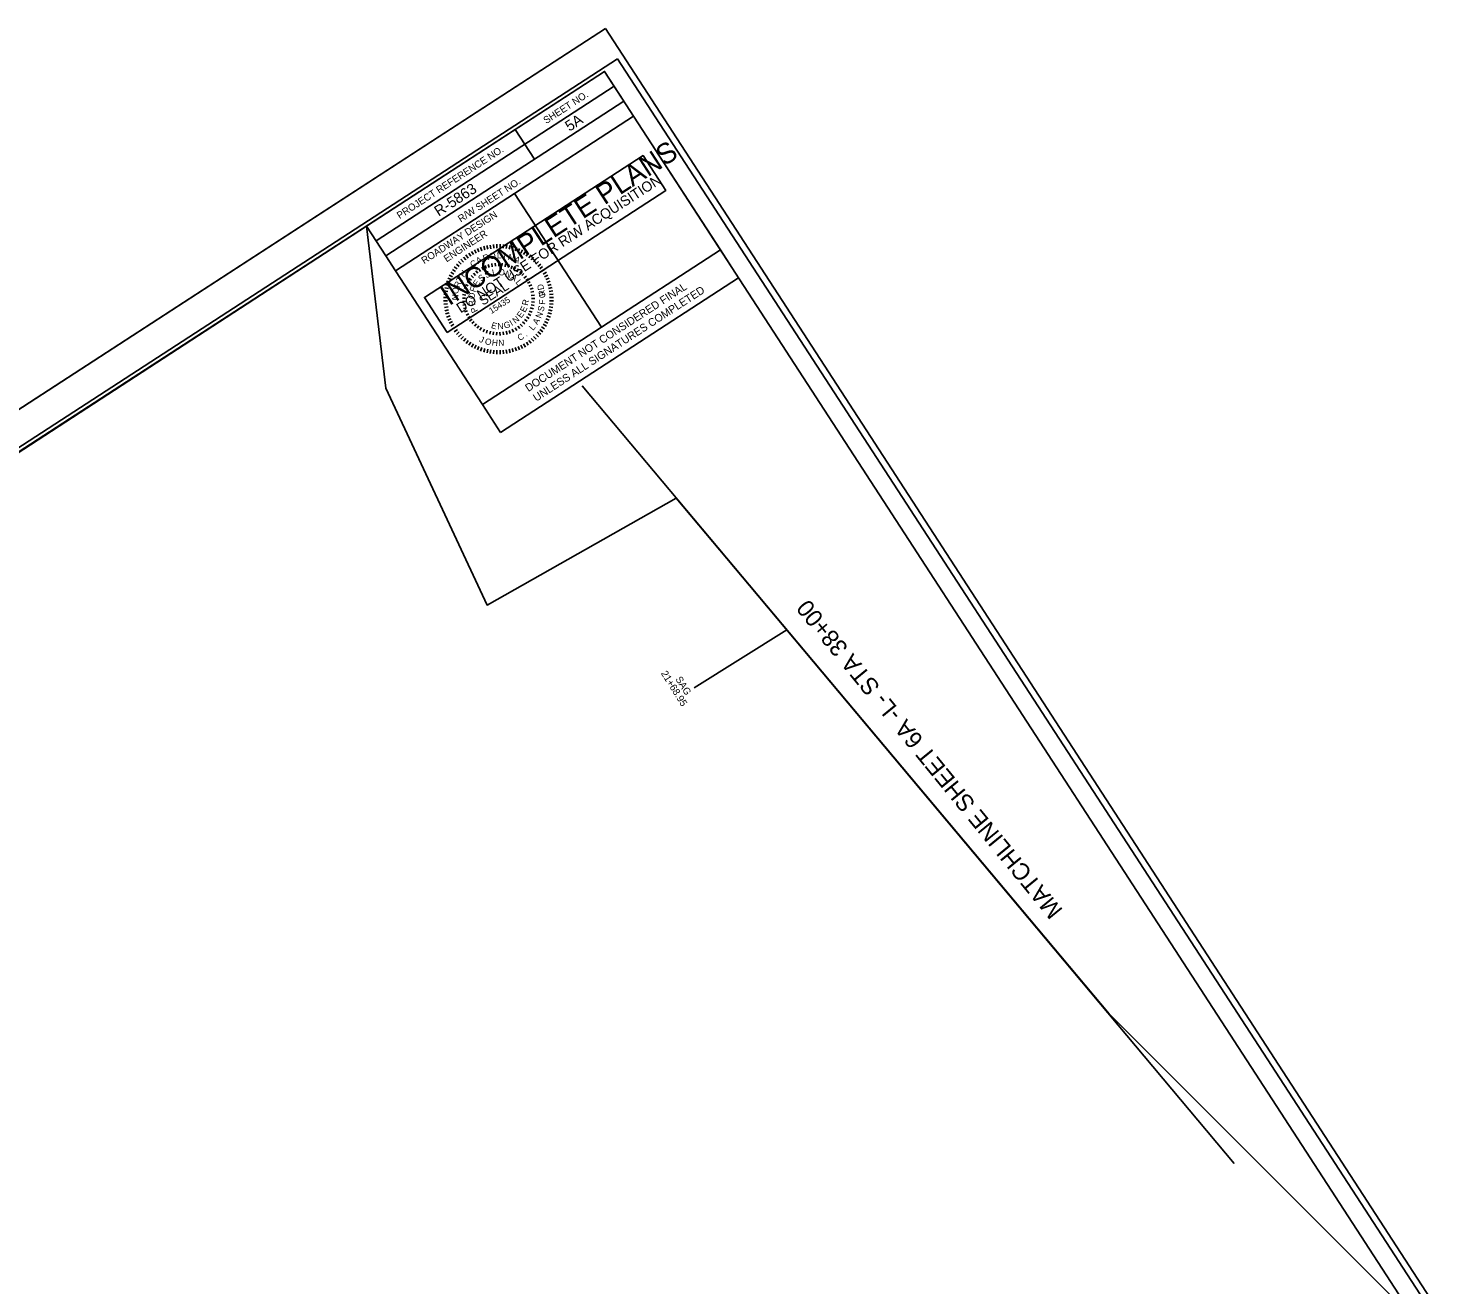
# Model space of a CAD drawing. Extents: x 555170 to 557181, y 503234 to 505074.
# Drawn here: x 556175 to 557181, y 504189 to 505074 of the extents above; entities that cross this region are included whole.
import ezdxf

# ---------------------------------------------------------------- set-up
doc = ezdxf.new("R2010")
doc.units = 0
for name, color, linetype in [('Exist Horizontal Alignment', 7, 'Continuous'), ('Old_Level_2', 7, 'Continuous'), ('Pattern 1', 7, 'Continuous'), ('Prop Horizontal Alignment', 7, 'Continuous'), ('Prop Horizontal Alignment Curve and Spiral Data', 7, 'Continuous'), ('Prop Paved Shoulder', 7, 'Continuous'), ('Prop Roadway Bridge', 7, 'Continuous'), ('Prop Superelevation Label', 7, 'Continuous'), ('Scratch_Level_4', 7, 'Continuous'), ('Sheet North Arrow CELL', 7, 'Continuous'), ('Sheet Plot Border Inside CELL', 7, 'Continuous'), ('Sheet Plot Border Outside CELL', 7, 'Continuous')]:
    doc.layers.add(name, color=color, linetype=linetype)

msp = doc.modelspace()

# ---------------------------------------------------------------- linework, layer by layer
at = {"layer": 'Exist Horizontal Alignment'}
msp.add_lwpolyline([(556581.9, 505074), (555169.6, 504156.8), (555768.7, 503234.3), (557181.1, 504151.5)], close=True, dxfattribs=at)
at = {"layer": 'Old_Level_2'}
msp.add_line((556709.9, 504650), (556644.6, 504609.3), dxfattribs=at)
at = {"layer": 'Pattern 1'}
for p, q in [((556489.6, 504918), (556490.8, 504915.6)), ((556491.8, 504918.9), (556492.8, 504916.5)), ((556493.9, 504919.8), (556494.8, 504917.3)), ((556496.2, 504920.5), (556496.9, 504917.9)), ((556498.4, 504921), (556499, 504918.4)), ((556500.7, 504921.4), (556501.1, 504918.8)), ((556503.1, 504921.7), (556503.3, 504919.1)), ((556505.4, 504921.9), (556505.5, 504919.2)), ((556507.7, 504921.9), (556507.7, 504919.2)), ((556510.1, 504921.7), (556509.8, 504919.1)), ((556512.4, 504921.5), (556512, 504918.9)), ((556514.7, 504921), (556514.1, 504918.5)), ((556517, 504920.5), (556516.2, 504917.9)), ((556519.2, 504919.8), (556518.3, 504917.3)), ((556521.4, 504919), (556520.4, 504916.5)), ((556523.5, 504918), (556522.4, 504915.6)), ((556476.9, 504908), (556478.9, 504906.3)), ((556478.4, 504909.7), (556480.3, 504907.9)), ((556480.1, 504911.4), (556481.9, 504909.4)), ((556481.8, 504912.9), (556483.5, 504910.9)), ((556483.6, 504914.4), (556485.2, 504912.2)), ((556485.6, 504915.7), (556487, 504913.5)), ((556487.6, 504916.9), (556488.9, 504914.6)), ((556501.8, 504908.3), (556502.2, 504906.1)), ((556504.3, 504908.6), (556504.5, 504906.4)), ((556506.7, 504908.7), (556506.7, 504906.5)), ((556509.2, 504908.6), (556509, 504906.4)), ((556511.6, 504908.2), (556511.2, 504906)), ((556525.6, 504916.9), (556524.3, 504914.6)), ((556527.6, 504915.7), (556526.1, 504913.5)), ((556529.5, 504914.4), (556527.9, 504912.3)), ((556531.3, 504912.9), (556529.6, 504910.9)), ((556533.1, 504911.4), (556531.3, 504909.5)), ((556534.7, 504909.7), (556532.8, 504907.9)), ((556536.3, 504908), (556534.3, 504906.3)), ((556470.8, 504898), (556473.3, 504897)), ((556471.8, 504900.1), (556474.2, 504899)), ((556472.9, 504902.2), (556475.2, 504900.9)), ((556474.1, 504904.2), (556476.3, 504902.8)), ((556475.4, 504906.1), (556477.5, 504904.6)), ((556485.7, 504897.8), (556487.5, 504896.6)), ((556487.2, 504899.8), (556488.9, 504898.3)), ((556488.9, 504901.6), (556490.4, 504900)), ((556490.7, 504903.2), (556492.1, 504901.5)), ((556492.7, 504904.6), (556493.9, 504902.8)), ((556493.9, 504902.8), (556492.7, 504904.6)), ((556494.9, 504905.9), (556495.9, 504903.9)), ((556497.1, 504906.9), (556497.9, 504904.8)), ((556499.4, 504907.7), (556500, 504905.6)), ((556514, 504907.6), (556513.4, 504905.5)), ((556516.3, 504906.8), (556515.5, 504904.7)), ((556518.6, 504905.7), (556517.5, 504903.8)), ((556520.7, 504904.5), (556519.5, 504902.6)), ((556522.7, 504903), (556521.3, 504901.3)), ((556524.5, 504901.4), (556523, 504899.8)), ((556526.2, 504899.5), (556524.5, 504898.1)), ((556537.7, 504906.2), (556535.6, 504904.6)), ((556539.1, 504904.2), (556536.8, 504902.8)), ((556540.3, 504902.2), (556538, 504900.9)), ((556541.4, 504900.2), (556539, 504899)), ((556542.3, 504898), (556539.9, 504897)), ((556468.3, 504889), (556470.9, 504888.6)), ((556468.8, 504891.3), (556471.3, 504890.8)), ((556469.3, 504893.6), (556471.9, 504892.9)), ((556470, 504895.8), (556472.5, 504895)), ((556481.7, 504888.8), (556483.9, 504888.4)), ((556482.4, 504891.2), (556484.5, 504890.5)), ((556483.3, 504893.5), (556485.3, 504892.6)), ((556484.4, 504895.7), (556486.3, 504894.6)), ((556527.7, 504897.6), (556525.8, 504896.3)), ((556528.9, 504895.5), (556527, 504894.4)), ((556528, 504892.5), (556530, 504893.3)), ((556530.9, 504891), (556528.8, 504890.3)), ((556531.5, 504888.6), (556529.4, 504888.1)), ((556543.1, 504895.9), (556540.7, 504895)), ((556543.8, 504893.6), (556541.3, 504892.9)), ((556544.4, 504891.4), (556541.8, 504890.8)), ((556544.8, 504889.1), (556542.2, 504888.7)), ((556467.9, 504884.4), (556470.6, 504884.3)), ((556467.9, 504882), (556470.6, 504882.1)), ((556468.1, 504886.7), (556470.7, 504886.5)), ((556468.1, 504879.7), (556470.7, 504879.9)), ((556468.4, 504877.4), (556471, 504877.8)), ((556481.1, 504884), (556483.3, 504883.9)), ((556481.2, 504881.5), (556483.3, 504881.6)), ((556481.3, 504886.4), (556483.5, 504886.1)), ((556481.4, 504879.1), (556483.6, 504879.4)), ((556531.7, 504878.8), (556529.5, 504879.2)), ((556531.9, 504886.1), (556529.7, 504885.9)), ((556532, 504881.2), (556529.8, 504881.4)), ((556532.1, 504883.7), (556529.9, 504883.6)), ((556544.8, 504877.4), (556542.2, 504877.8)), ((556545.1, 504886.7), (556542.5, 504886.5)), ((556545.1, 504879.7), (556542.5, 504880)), ((556545.3, 504884.4), (556542.6, 504884.3)), ((556545.3, 504882.1), (556542.6, 504882.1)), ((556468.8, 504875.1), (556471.4, 504875.6)), ((556469.3, 504872.8), (556471.9, 504873.5)), ((556470, 504870.6), (556472.5, 504871.4)), ((556470.9, 504868.4), (556473.3, 504869.4)), ((556482, 504876.6), (556484.1, 504877.2)), ((556482.7, 504874.3), (556484.8, 504875.1)), ((556483.7, 504872), (556485.6, 504873)), ((556484.9, 504869.9), (556486.7, 504871)), ((556486.2, 504867.8), (556488, 504869.2)), ((556526.8, 504867.6), (556525, 504869)), ((556528.2, 504869.6), (556526.3, 504870.8)), ((556529.4, 504871.8), (556527.4, 504872.8)), ((556530.4, 504874), (556528.3, 504874.8)), ((556531.2, 504876.4), (556529, 504877)), ((556542.3, 504868.4), (556539.9, 504869.4)), ((556543.2, 504870.6), (556540.7, 504871.5)), ((556543.9, 504872.9), (556541.3, 504873.6)), ((556544.4, 504875.1), (556541.8, 504875.7)), ((556471.8, 504866.3), (556474.2, 504867.4)), ((556472.9, 504864.2), (556475.2, 504865.5)), ((556474.1, 504862.2), (556476.3, 504863.6)), ((556475.4, 504860.3), (556477.6, 504861.8)), ((556476.9, 504858.4), (556478.9, 504860.1)), ((556478.4, 504856.7), (556480.4, 504858.5)), ((556487.8, 504866), (556489.4, 504867.4)), ((556489.6, 504864.2), (556491, 504865.9)), ((556491.5, 504862.7), (556492.8, 504864.4)), ((556493.5, 504861.3), (556494.7, 504863.2)), ((556495.7, 504860.2), (556496.7, 504862.1)), ((556498, 504859.2), (556498.7, 504861.3)), ((556500.4, 504858.5), (556500.9, 504860.6)), ((556502.8, 504858), (556503.1, 504860.2)), ((556505.2, 504857.8), (556505.3, 504859.9)), ((556507.7, 504857.7), (556507.6, 504859.9)), ((556510.1, 504858), (556509.8, 504860.1)), ((556512.6, 504858.4), (556512, 504860.6)), ((556514.2, 504861.2), (556514.9, 504859.1)), ((556517.2, 504860), (556516.3, 504862)), ((556519.4, 504861.2), (556518.3, 504863.1)), ((556521.5, 504862.5), (556520.2, 504864.3)), ((556523.4, 504864), (556521.9, 504865.7)), ((556525.2, 504865.8), (556523.6, 504867.3)), ((556534.8, 504856.7), (556532.9, 504858.5)), ((556536.3, 504858.5), (556534.3, 504860.2)), ((556537.8, 504860.3), (556535.6, 504861.9)), ((556539.1, 504862.2), (556536.9, 504863.7)), ((556540.3, 504864.2), (556538, 504865.5)), ((556541.4, 504866.3), (556539, 504867.5)), ((556480.1, 504855), (556481.9, 504856.9)), ((556481.8, 504853.5), (556483.5, 504855.5)), ((556483.7, 504852), (556485.2, 504854.2)), ((556485.6, 504850.7), (556487, 504852.9)), ((556487.6, 504849.5), (556488.9, 504851.8)), ((556489.7, 504848.4), (556490.8, 504850.8)), ((556491.8, 504847.5), (556492.8, 504849.9)), ((556494, 504846.6), (556494.9, 504849.1)), ((556496.2, 504845.9), (556496.9, 504848.5)), ((556498.5, 504845.4), (556499, 504848)), ((556500.8, 504845), (556501.2, 504847.6)), ((556512.4, 504845), (556512, 504847.6)), ((556514.7, 504845.4), (556514.2, 504848)), ((556517, 504846), (556516.3, 504848.5)), ((556519.2, 504846.7), (556518.4, 504849.1)), ((556521.4, 504847.5), (556520.4, 504849.9)), ((556523.5, 504848.4), (556522.4, 504850.8)), ((556525.6, 504849.5), (556524.3, 504851.8)), ((556527.6, 504850.7), (556526.2, 504853)), ((556529.5, 504852.1), (556528, 504854.2)), ((556531.4, 504853.5), (556529.7, 504855.5)), ((556533.1, 504855.1), (556531.3, 504857)), ((556503.1, 504844.7), (556503.3, 504847.3)), ((556505.4, 504844.5), (556505.5, 504847.2)), ((556507.8, 504844.5), (556507.7, 504847.2)), ((556510.1, 504844.7), (556509.9, 504847.3))]:
    msp.add_line(p, q, dxfattribs=at)
at = {"layer": 'Prop Horizontal Alignment'}
msp.add_line((556581.9, 505074), (555169.6, 504156.8), dxfattribs=at)
at = {"layer": 'Prop Horizontal Alignment Curve and Spiral Data'}
msp.add_lwpolyline([(556470.4, 504859.8), (556454.4, 504884.4), (556608.5, 504984.5), (556624.5, 504959.9)], close=True, dxfattribs=at)
at = {"layer": 'Prop Paved Shoulder'}
for p, q in [((556565.6, 504822.1), (556936.9, 504379.3)), ((557025.1, 504274), (556639.6, 504733.8))]:
    msp.add_line(p, q, dxfattribs=at)
at = {"layer": 'Prop Superelevation Label'}
msp.add_lwpolyline([(555838.5, 503433.5), (555757.6, 503602.9), (555641.4, 503854.9), (555665.1, 503867.4), (555636.4, 503915.7), (555617.1, 503909), (555456.4, 504257.6), (555437.1, 504299.2), (556413.5, 504934.8), (556427.1, 504820.4), (556498.5, 504667.6), (556631.8, 504743), (556936.9, 504379.3), (557153.2, 504163.2), (555896, 503346.8)], close=True, dxfattribs=at)
at = {"layer": 'Scratch_Level_4'}
for p, q in [((556495.2, 504809), (556663, 504917.9)), ((556663, 504917.9), (556675.8, 504898.2)), ((556675.8, 504898.2), (556508, 504789.3)), ((556508, 504789.3), (556495.2, 504809))]:
    msp.add_line(p, q, dxfattribs=at)
at = {"layer": 'Sheet North Arrow CELL'}
msp.add_lwpolyline([(556590.4, 505052.7), (555192.8, 504145.1), (555767.4, 503260.2), (557165.1, 504167.9)], close=True, dxfattribs=at)
at = {"layer": 'Sheet Plot Border Outside CELL'}
for p, q in [((556420.4, 504924.3), (556588.1, 505033.3)), ((556427.2, 504913.8), (556594.9, 505022.8)), ((556427.2, 504913.8), (556594.9, 505022.8)), ((556518.4, 505002.9), (556532, 504981.9)), ((556517.9, 504957.8), (556579.1, 504863.5)), ((556427.2, 504913.8), (556434, 504903.3))]:
    msp.add_line(p, q, dxfattribs=at)
for points in [[(556581.3, 505043.8), (555323.3, 504226.8), (555895.2, 503346.2), (557153.2, 504163.2)], [(556413.5, 504934.8), (556581.3, 505043.8), (556594.9, 505022.8), (556427.2, 504913.8)], [(556517.9, 504957.8), (556601.7, 505012.3), (556663, 504917.9), (556579.2, 504863.5)], [(556434, 504903.3), (556517.9, 504957.8), (556579.2, 504863.5), (556495.2, 504809)]]:
    msp.add_lwpolyline(points, close=True, dxfattribs=at)

# ---------------------------------------------------------------- texts
at = {"layer": 'Old_Level_2'}
for s, p in [('21+68.95', (556620.9, 504619.4)), ('SAG', (556631.1, 504615.4))]:
    msp.add_text(s, height=5, rotation=301.9508, dxfattribs=at).set_placement(p)
at = {"layer": 'Pattern 1'}
for s, height, rotation, p in [('C', 4.39, 30.2778, (556488.1, 504905.3)), ('A', 4.39, 30.2778, (556492.2, 504907.9)), ('R', 4.39, 18.2685, (556496.4, 504909.8)), ('O', 4.39, 15.2117, (556500.7, 504911.1)), ('L', 4.39, 2.0754, (556505.5, 504911.9)), ('I', 4.39, 352.4999, (556509.8, 504911.7)), ('N', 4.39, 343.2055, (556512.8, 504911.1)), ('A', 4.39, 333.4379, (556517, 504910)), ('T', 4.39, 63.4204, (556480.4, 504894.7)), ('H', 4.39, 53.9885, (556482.3, 504898.2)), ('S', 4.39, 40.569, (556494.5, 504895.3)), ('S', 4.39, 25.2727, (556498, 504897.9)), ('I', 4.39, 9.9765, (556502.4, 504899.7)), ('O', 4.39, 354.6802, (556506.3, 504900.2)), ('N', 4.39, 339.384, (556510.7, 504899.5)), ('A', 4.39, 324.0877, (556514.7, 504897.8)), ('O', 4.39, 84.6381, (556478.2, 504886.8)), ('R', 4.39, 71.5814, (556479.2, 504891)), ('O', 4.39, 86.4577, (556489.7, 504883.2)), ('F', 4.39, 71.1614, (556490.2, 504887.8)), ('E', 4.39, 55.8652, (556491.8, 504891.8)), ('SEAL', 6.59, 32.9208, (556495.6, 504878.5)), ('L', 4.39, 308.7915, (556518.3, 504895)), (' RD', 4.39, 102.5933, (556540.1, 504884.4)), ('O ', 4.39, 93.9205, (556539.6, 504884.1)), ('N', 4.39, 86.5976, (556478.1, 504882.3)), ('R', 4.39, 101.7539, (556490.4, 504878.9)), ('15435', 4.39, 32.9208, (556501.6, 504872.7)), ('E', 4.39, 63.7146, (556525.4, 504873.5)), ('R', 4.39, 77.4857, (556527.3, 504878.4)), ('S', 4.39, 76.2453, (556538.3, 504874.1)), ('F', 4.39, 85.1279, (556539.4, 504879.2)), ('P', 4.39, 117.0502, (556492.2, 504874.9)), ('G', 4.39, 12.6122, (556510.8, 504862.5)), ('I', 4.39, 30.707, (556515.9, 504864.2)), ('N', 4.39, 38.3367, (556518.5, 504865.7)), ('E', 4.39, 53.7288, (556522.6, 504869.5)), ('A', 4.39, 58.54, (556534, 504864.8)), ('N', 4.39, 67.3626, (556536.5, 504869.3)), ('E', 4.39, 342.9909, (556501, 504863)), ('N', 4.39, 3.846, (556506, 504861.9)), ('C', 4.39, 29.0108, (556521.4, 504853.7)), ('.', 4.39, 36.7531, (556526.1, 504856.6)), ('L', 4.39, 49.5374, (556530.9, 504860.8)), ('J', 4.39, 336.8558, (556492.6, 504853.3)), ('O', 4.39, 344.9277, (556496.6, 504851.7)), ('H', 4.39, 353.5704, (556501.7, 504850.6)), ('N', 4.39, 2.243, (556506.5, 504850.2))]:
    msp.add_text(s, height=height, rotation=rotation, dxfattribs=at).set_placement(p)
at = {"layer": 'Prop Horizontal Alignment Curve and Spiral Data'}
for s, height, p in [('INCOMPLETE PLANS', 14.4, (556471.8, 504878.2)), ('DO NOT USE FOR R/W ACQUISITION', 7.2, (556479.9, 504873.1))]:
    msp.add_text(s, height=height, rotation=33.0007, dxfattribs=at).set_placement(p)
at = {"layer": 'Prop Roadway Bridge'}
msp.add_text('MATCHLINE SHEET 6A -L- STA 38+00', height=12, rotation=129.2733, dxfattribs=at).set_placement((556904.8, 504452.6))
at = {"layer": 'Scratch_Level_4'}
for s, p in [('DOCUMENT NOT CONSIDERED FINAL', (556527.6, 504817.7)), ('UNLESS ALL SIGNATURES COMPLETED', (556533.2, 504810.8))]:
    msp.add_text(s, height=5.5, rotation=33.0007, dxfattribs=at).set_placement(p)
at = {"layer": 'Sheet Plot Border Inside CELL'}
for s, p in [('5A', (556556.6, 505001.2)), ('R-5863', (556464.4, 504941.3))]:
    msp.add_text(s, height=7.5, rotation=33.0007, dxfattribs=at).set_placement(p)
at = {"layer": 'Sheet Plot Border Outside CELL'}
for s, p in [('SHEET NO.', (556540.2, 505006.6)), ('PROJECT REFERENCE NO.', (556436.9, 504939.6)), ('R/W SHEET NO.', (556480, 504937.2)), ('ROADWAY DESIGN', (556454.2, 504907.8)), ('ENGINEER', (556470, 504909.1))]:
    msp.add_text(s, height=5, rotation=33.0007, dxfattribs=at).set_placement(p)

doc.saveas('drawing.dxf')
